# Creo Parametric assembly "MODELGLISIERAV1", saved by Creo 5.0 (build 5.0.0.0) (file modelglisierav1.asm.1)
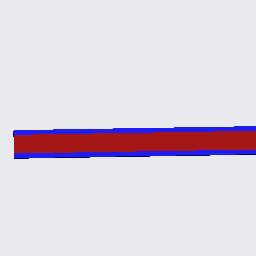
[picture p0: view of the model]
Units: Inch lbm Second (Pro/E Default); INCH, POUND, SECS

Other parameters: TRANSLATION1_STATIC_FRICTION, TRANSLATION1_KINETIC_FRICTION, TRANSLATION1_RESTITUTION, TRANSLATION1_MINIMUM_LIMIT, TRANSLATION1_MAXIMUM_LIMIT, TRANSLATION1_ZERO_POSITION

Created from: INLBS_ASM_DESIGN.ASM

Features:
  1. datum plane "ASM_RIGHT"
  2. datum plane "ASM_TOP"
  3. datum plane "ASM_FRONT"
  4. coordinate system
  5. component "PRT0001"
  6. component "PRT0002"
